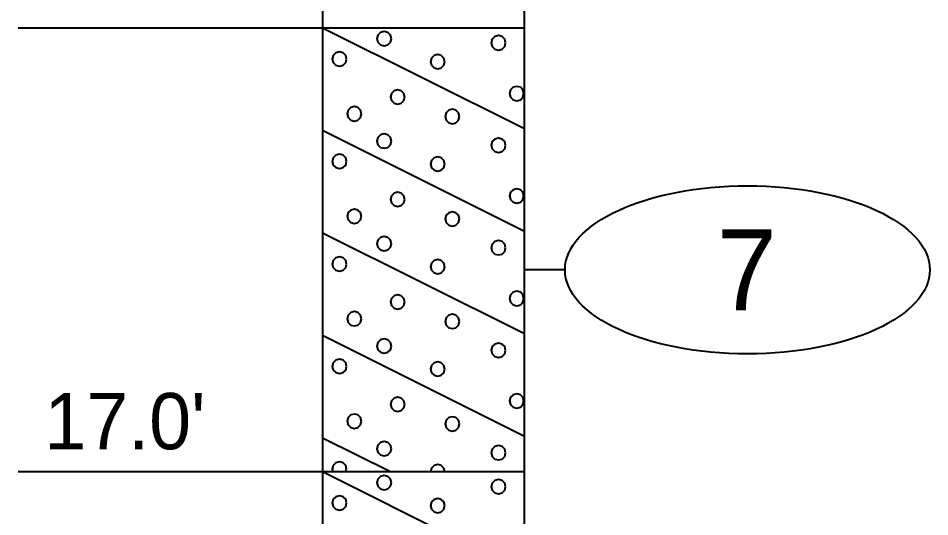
# Model space of a CAD drawing. Extents: x -76 to 974, y -1080 to -735.
# Drawn here: x -70.92 to -59.64, y -784.27 to -778.09 of the extents above; entities that cross this region are included whole.
import ezdxf
from ezdxf.enums import TextEntityAlignment as Align

# ---------------------------------------------------------------- set-up
doc = ezdxf.new("R2010")
doc.units = 0
doc.header["$LTSCALE"] = 0.36
doc.layers.add('27', color=7, linetype='Continuous', lineweight=40)

msp = doc.modelspace()

# ---------------------------------------------------------------- linework, layer by layer
at = {"layer": '27'}
for p, q in [((-67.154, -766.7053), (-67.154, -778.2053)), ((-64.654, -778.2053), (-64.654, -766.7053)), ((-70.9214, -778.2053), (-67.154, -778.2053)), ((-67.154, -778.2053), (-64.654, -778.2053)), ((-67.154, -778.2053), (-64.654, -779.4553)), ((-67.154, -778.2053), (-67.154, -783.7053)), ((-64.654, -783.7053), (-64.654, -778.2053)), ((-67.154, -779.4753), (-64.654, -780.7253)), ((-67.154, -780.7453), (-64.654, -781.9953)), ((-64.154, -781.2053), (-64.654, -781.2053)), ((-67.154, -782.0153), (-64.654, -783.2653)), ((-67.154, -783.2853), (-66.314, -783.7053)), ((-70.9214, -783.7053), (-67.154, -783.7053)), ((-67.154, -783.7053), (-64.654, -783.7053)), ((-67.154, -783.7053), (-64.654, -784.9553)), ((-67.154, -783.7053), (-67.154, -798.7053)), ((-64.654, -798.7053), (-64.654, -783.7053))]:
    msp.add_line(p, q, dxfattribs=at)
for points in [[(-66.3033, -778.3416), (-66.3152, -778.2972), (-66.3477, -778.2646), (-66.3922, -778.2527), (-66.4366, -778.2646), (-66.4692, -778.2972), (-66.4811, -778.3416), (-66.4692, -778.3861), (-66.4366, -778.4186), (-66.3922, -778.4305), (-66.3477, -778.4186), (-66.3152, -778.3861)], [(-64.8885, -778.3925), (-64.9004, -778.3481), (-64.9329, -778.3155), (-64.9774, -778.3036), (-65.0218, -778.3155), (-65.0543, -778.3481), (-65.0663, -778.3925), (-65.0543, -778.437), (-65.0218, -778.4695), (-64.9774, -778.4814), (-64.9329, -778.4695), (-64.9004, -778.437)], [(-66.8564, -778.5934), (-66.8683, -778.5489), (-66.9008, -778.5164), (-66.9453, -778.5045), (-66.9897, -778.5164), (-67.0223, -778.5489), (-67.0342, -778.5934), (-67.0223, -778.6378), (-66.9897, -778.6704), (-66.9453, -778.6823), (-66.9008, -778.6704), (-66.8683, -778.6378)], [(-65.641, -778.6264), (-65.653, -778.582), (-65.6855, -778.5495), (-65.7299, -778.5375), (-65.7744, -778.5495), (-65.8069, -778.582), (-65.8188, -778.6264), (-65.8069, -778.6709), (-65.7744, -778.7034), (-65.7299, -778.7153), (-65.6855, -778.7034), (-65.653, -778.6709)], [(-66.1368, -779.0638), (-66.1487, -779.0193), (-66.1813, -778.9868), (-66.2257, -778.9749), (-66.2702, -778.9868), (-66.3027, -779.0193), (-66.3146, -779.0638), (-66.3027, -779.1082), (-66.2702, -779.1408), (-66.2257, -779.1527), (-66.1813, -779.1408), (-66.1487, -779.1082)], [(-64.6622, -779.0205), (-64.6741, -778.9761), (-64.7066, -778.9436), (-64.7511, -778.9316), (-64.7955, -778.9436), (-64.8281, -778.9761), (-64.84, -779.0205), (-64.8281, -779.065), (-64.7955, -779.0975), (-64.7511, -779.1094), (-64.7066, -779.0975), (-64.6741, -779.065)], [(-66.672, -779.2723), (-66.684, -779.2278), (-66.7165, -779.1953), (-66.7609, -779.1834), (-66.8054, -779.1953), (-66.8379, -779.2278), (-66.8498, -779.2723), (-66.8379, -779.3167), (-66.8054, -779.3492), (-66.7609, -779.3612), (-66.7165, -779.3492), (-66.684, -779.3167)], [(-65.4593, -779.3053), (-65.4712, -779.2609), (-65.5037, -779.2283), (-65.5482, -779.2164), (-65.5926, -779.2283), (-65.6251, -779.2609), (-65.6371, -779.3053), (-65.6251, -779.3498), (-65.5926, -779.3823), (-65.5482, -779.3942), (-65.5037, -779.3823), (-65.4712, -779.3498)], [(-66.3034, -779.6104), (-66.3153, -779.566), (-66.3478, -779.5334), (-66.3923, -779.5215), (-66.4367, -779.5334), (-66.4693, -779.566), (-66.4812, -779.6104), (-66.4693, -779.6549), (-66.4367, -779.6874), (-66.3923, -779.6993), (-66.3478, -779.6874), (-66.3153, -779.6549)], [(-64.8885, -779.6613), (-64.9004, -779.6168), (-64.9329, -779.5843), (-64.9774, -779.5724), (-65.0218, -779.5843), (-65.0543, -779.6168), (-65.0663, -779.6613), (-65.0543, -779.7057), (-65.0218, -779.7383), (-64.9774, -779.7502), (-64.9329, -779.7383), (-64.9004, -779.7057)], [(-66.8564, -779.8621), (-66.8683, -779.8177), (-66.9008, -779.7851), (-66.9453, -779.7732), (-66.9897, -779.7851), (-67.0223, -779.8177), (-67.0342, -779.8621), (-67.0223, -779.9066), (-66.9897, -779.9391), (-66.9453, -779.951), (-66.9008, -779.9391), (-66.8683, -779.9066)], [(-65.641, -779.8952), (-65.653, -779.8507), (-65.6855, -779.8182), (-65.7299, -779.8063), (-65.7744, -779.8182), (-65.8069, -779.8507), (-65.8188, -779.8952), (-65.8069, -779.9396), (-65.7744, -779.9722), (-65.7299, -779.9841), (-65.6855, -779.9722), (-65.653, -779.9396)], [(-66.1368, -780.3325), (-66.1487, -780.288), (-66.1813, -780.2555), (-66.2257, -780.2436), (-66.2702, -780.2555), (-66.3027, -780.288), (-66.3146, -780.3325), (-66.3027, -780.3769), (-66.2702, -780.4095), (-66.2257, -780.4214), (-66.1813, -780.4095), (-66.1487, -780.3769)], [(-64.6622, -780.2893), (-64.6741, -780.2448), (-64.7066, -780.2123), (-64.7511, -780.2004), (-64.7955, -780.2123), (-64.8281, -780.2448), (-64.84, -780.2893), (-64.8281, -780.3337), (-64.7955, -780.3663), (-64.7511, -780.3782), (-64.7066, -780.3663), (-64.6741, -780.3337)], [(-66.672, -780.541), (-66.684, -780.4965), (-66.7165, -780.464), (-66.7609, -780.4521), (-66.8054, -780.464), (-66.8379, -780.4965), (-66.8498, -780.541), (-66.8379, -780.5854), (-66.8054, -780.618), (-66.7609, -780.6299), (-66.7165, -780.618), (-66.684, -780.5854)], [(-65.4593, -780.574), (-65.4712, -780.5296), (-65.5037, -780.497), (-65.5482, -780.4851), (-65.5926, -780.497), (-65.6251, -780.5296), (-65.6371, -780.574), (-65.6251, -780.6185), (-65.5926, -780.651), (-65.5482, -780.6629), (-65.5037, -780.651), (-65.4712, -780.6185)], [(-66.3033, -780.8816), (-66.3152, -780.8372), (-66.3477, -780.8046), (-66.3922, -780.7927), (-66.4366, -780.8046), (-66.4692, -780.8372), (-66.4811, -780.8816), (-66.4692, -780.9261), (-66.4366, -780.9586), (-66.3922, -780.9705), (-66.3477, -780.9586), (-66.3152, -780.9261)], [(-64.8885, -780.9325), (-64.9004, -780.8881), (-64.9329, -780.8555), (-64.9774, -780.8436), (-65.0218, -780.8555), (-65.0543, -780.8881), (-65.0663, -780.9325), (-65.0543, -780.977), (-65.0218, -781.0095), (-64.9774, -781.0214), (-64.9329, -781.0095), (-64.9004, -780.977)], [(-66.8564, -781.1334), (-66.8683, -781.0889), (-66.9008, -781.0564), (-66.9453, -781.0445), (-66.9897, -781.0564), (-67.0223, -781.0889), (-67.0342, -781.1334), (-67.0223, -781.1778), (-66.9897, -781.2104), (-66.9453, -781.2223), (-66.9008, -781.2104), (-66.8683, -781.1778)], [(-65.641, -781.1664), (-65.653, -781.122), (-65.6855, -781.0895), (-65.7299, -781.0775), (-65.7744, -781.0895), (-65.8069, -781.122), (-65.8188, -781.1664), (-65.8069, -781.2109), (-65.7744, -781.2434), (-65.7299, -781.2553), (-65.6855, -781.2434), (-65.653, -781.2109)], [(-66.1368, -781.6038), (-66.1487, -781.5593), (-66.1813, -781.5268), (-66.2257, -781.5149), (-66.2702, -781.5268), (-66.3027, -781.5593), (-66.3146, -781.6038), (-66.3027, -781.6482), (-66.2702, -781.6808), (-66.2257, -781.6927), (-66.1813, -781.6808), (-66.1487, -781.6482)], [(-64.6622, -781.5605), (-64.6741, -781.5161), (-64.7066, -781.4836), (-64.7511, -781.4716), (-64.7955, -781.4836), (-64.8281, -781.5161), (-64.84, -781.5605), (-64.8281, -781.605), (-64.7955, -781.6375), (-64.7511, -781.6494), (-64.7066, -781.6375), (-64.6741, -781.605)], [(-66.672, -781.8123), (-66.684, -781.7678), (-66.7165, -781.7353), (-66.7609, -781.7234), (-66.8054, -781.7353), (-66.8379, -781.7678), (-66.8498, -781.8123), (-66.8379, -781.8567), (-66.8054, -781.8892), (-66.7609, -781.9012), (-66.7165, -781.8892), (-66.684, -781.8567)], [(-65.4593, -781.8453), (-65.4712, -781.8009), (-65.5037, -781.7683), (-65.5482, -781.7564), (-65.5926, -781.7683), (-65.6251, -781.8009), (-65.6371, -781.8453), (-65.6251, -781.8898), (-65.5926, -781.9223), (-65.5482, -781.9342), (-65.5037, -781.9223), (-65.4712, -781.8898)], [(-66.3034, -782.1504), (-66.3153, -782.106), (-66.3478, -782.0734), (-66.3923, -782.0615), (-66.4367, -782.0734), (-66.4693, -782.106), (-66.4812, -782.1504), (-66.4693, -782.1949), (-66.4367, -782.2274), (-66.3923, -782.2393), (-66.3478, -782.2274), (-66.3153, -782.1949)], [(-64.8885, -782.2013), (-64.9004, -782.1568), (-64.9329, -782.1243), (-64.9774, -782.1124), (-65.0218, -782.1243), (-65.0543, -782.1568), (-65.0663, -782.2013), (-65.0543, -782.2457), (-65.0218, -782.2783), (-64.9774, -782.2902), (-64.9329, -782.2783), (-64.9004, -782.2457)], [(-66.8564, -782.4021), (-66.8683, -782.3577), (-66.9008, -782.3251), (-66.9453, -782.3132), (-66.9897, -782.3251), (-67.0223, -782.3577), (-67.0342, -782.4021), (-67.0223, -782.4466), (-66.9897, -782.4791), (-66.9453, -782.491), (-66.9008, -782.4791), (-66.8683, -782.4466)], [(-65.641, -782.4352), (-65.653, -782.3907), (-65.6855, -782.3582), (-65.7299, -782.3463), (-65.7744, -782.3582), (-65.8069, -782.3907), (-65.8188, -782.4352), (-65.8069, -782.4796), (-65.7744, -782.5122), (-65.7299, -782.5241), (-65.6855, -782.5122), (-65.653, -782.4796)], [(-64.6622, -782.8293), (-64.6741, -782.7848), (-64.7066, -782.7523), (-64.7511, -782.7404), (-64.7955, -782.7523), (-64.8281, -782.7848), (-64.84, -782.8293), (-64.8281, -782.8737), (-64.7955, -782.9063), (-64.7511, -782.9182), (-64.7066, -782.9063), (-64.6741, -782.8737)], [(-66.1368, -782.8725), (-66.1487, -782.828), (-66.1813, -782.7955), (-66.2257, -782.7836), (-66.2702, -782.7955), (-66.3027, -782.828), (-66.3146, -782.8725), (-66.3027, -782.9169), (-66.2702, -782.9495), (-66.2257, -782.9614), (-66.1813, -782.9495), (-66.1487, -782.9169)], [(-66.672, -783.081), (-66.684, -783.0365), (-66.7165, -783.004), (-66.7609, -782.9921), (-66.8054, -783.004), (-66.8379, -783.0365), (-66.8498, -783.081), (-66.8379, -783.1254), (-66.8054, -783.158), (-66.7609, -783.1699), (-66.7165, -783.158), (-66.684, -783.1254)], [(-65.4593, -783.114), (-65.4712, -783.0696), (-65.5037, -783.037), (-65.5482, -783.0251), (-65.5926, -783.037), (-65.6251, -783.0696), (-65.6371, -783.114), (-65.6251, -783.1585), (-65.5926, -783.191), (-65.5482, -783.2029), (-65.5037, -783.191), (-65.4712, -783.1585)], [(-66.3033, -783.4216), (-66.3152, -783.3772), (-66.3477, -783.3446), (-66.3922, -783.3327), (-66.4366, -783.3446), (-66.4692, -783.3772), (-66.4811, -783.4216), (-66.4692, -783.4661), (-66.4366, -783.4986), (-66.3922, -783.5105), (-66.3477, -783.4986), (-66.3152, -783.4661)], [(-64.8885, -783.4725), (-64.9004, -783.4281), (-64.9329, -783.3955), (-64.9774, -783.3836), (-65.0218, -783.3955), (-65.0543, -783.4281), (-65.0663, -783.4725), (-65.0543, -783.517), (-65.0218, -783.5495), (-64.9774, -783.5614), (-64.9329, -783.5495), (-64.9004, -783.517)], [(-66.8564, -783.6734), (-66.8683, -783.6289), (-66.9008, -783.5964), (-66.9453, -783.5845), (-66.9897, -783.5964), (-67.0223, -783.6289), (-67.0342, -783.6734), (-67.0256, -783.7053), (-66.8649, -783.7053)], [(-65.653, -783.662), (-65.6855, -783.6295), (-65.7299, -783.6175), (-65.7744, -783.6295), (-65.8069, -783.662), (-65.8185, -783.7053), (-65.6414, -783.7053)], [(-66.3033, -783.8416), (-66.3152, -783.7972), (-66.3477, -783.7646), (-66.3922, -783.7527), (-66.4366, -783.7646), (-66.4692, -783.7972), (-66.4811, -783.8416), (-66.4692, -783.8861), (-66.4366, -783.9186), (-66.3922, -783.9305), (-66.3477, -783.9186), (-66.3152, -783.8861)], [(-64.8885, -783.8925), (-64.9004, -783.8481), (-64.9329, -783.8155), (-64.9774, -783.8036), (-65.0218, -783.8155), (-65.0543, -783.8481), (-65.0663, -783.8925), (-65.0543, -783.937), (-65.0218, -783.9695), (-64.9774, -783.9814), (-64.9329, -783.9695), (-64.9004, -783.937)], [(-66.8564, -784.0934), (-66.8683, -784.0489), (-66.9008, -784.0164), (-66.9453, -784.0045), (-66.9897, -784.0164), (-67.0223, -784.0489), (-67.0342, -784.0934), (-67.0223, -784.1378), (-66.9897, -784.1704), (-66.9453, -784.1823), (-66.9008, -784.1704), (-66.8683, -784.1378)], [(-65.641, -784.1264), (-65.653, -784.082), (-65.6855, -784.0495), (-65.7299, -784.0375), (-65.7744, -784.0495), (-65.8069, -784.082), (-65.8188, -784.1264), (-65.8069, -784.1709), (-65.7744, -784.2034), (-65.7299, -784.2153), (-65.6855, -784.2034), (-65.653, -784.1709)]]:
    msp.add_lwpolyline(points, close=True, dxfattribs=at)
msp.add_ellipse((-61.8966, -781.2053), major_axis=(2.2574, 0), ratio=0.461538, dxfattribs=at)

# ---------------------------------------------------------------- texts
msp.add_text('7', height=1, dxfattribs=at).set_placement((-61.9039, -781.7052), align=Align.CENTER)
msp.add_text("17.0'", height=0.6976, dxfattribs=at).set_placement((-70.5974, -783.4289))

doc.saveas('drawing.dxf')
